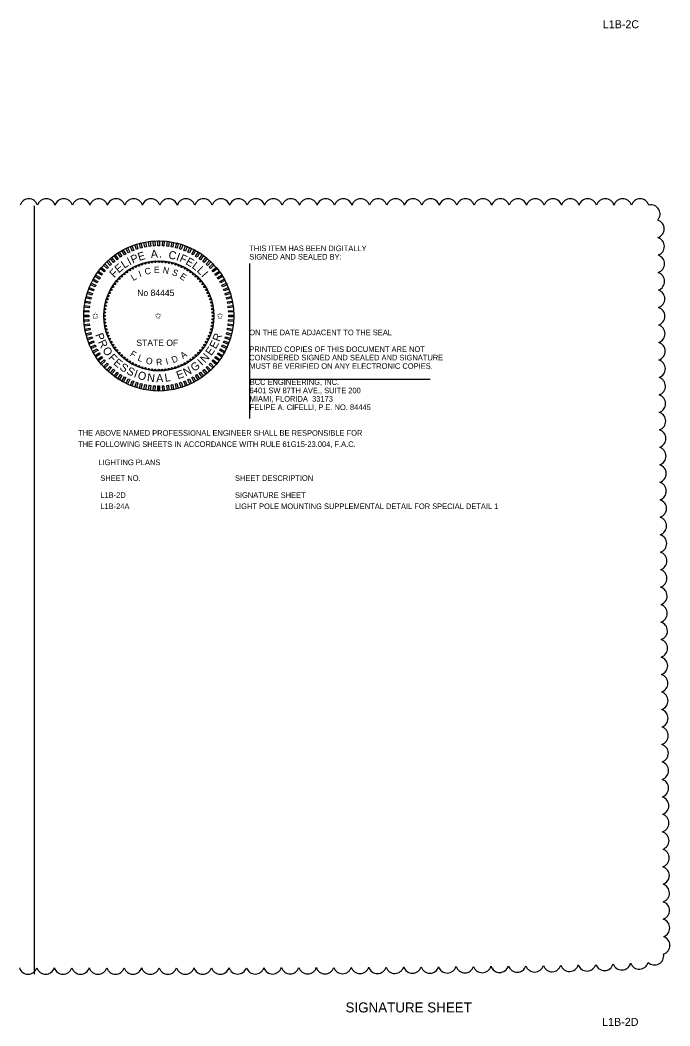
# Model space of a CAD drawing. Extents: x -811.2 to -755.6, y -2295.2 to -2235.1.
# Drawn here: x -803.27 to -795.14, y -2295.15 to -2282.59 of the extents above; entities that cross this region are included whole.
import ezdxf

# ---------------------------------------------------------------- set-up
doc = ezdxf.new("R2010")
doc.units = 0
for name, color, linetype in [('Cloud_dp', 7, 'Continuous'), ('Logo_dp', 7, 'Continuous'), ('NonPlottingEle_dp', 7, 'Continuous'), ('ScratchEle_dp', 7, 'Continuous'), ('SheetBorder_dp', 7, 'Continuous'), ('TextMisc', 7, 'Continuous'), ('TextNotes', 7, 'Continuous'), ('TextShtNo', 7, 'Continuous')]:
    doc.layers.add(name, color=color, linetype=linetype)

msp = doc.modelspace()

# ---------------------------------------------------------------- linework, layer by layer
at = {"layer": 'Cloud_dp'}
for centre, start, end in [((-803.157, -2284.933), 17.5, 162.5), ((-802.939, -2284.933), 17.5, 162.5), ((-802.721, -2284.933), 17.5, 162.5), ((-802.502, -2284.933), 17.5, 162.5), ((-802.284, -2284.933), 17.5, 162.5), ((-802.066, -2284.933), 17.5, 162.5), ((-801.847, -2284.933), 17.5, 162.5), ((-801.629, -2284.933), 17.5, 162.5), ((-801.411, -2284.933), 17.5, 162.5), ((-801.192, -2284.933), 17.5, 162.5), ((-800.974, -2284.933), 17.5, 162.5), ((-800.756, -2284.933), 17.5, 162.5), ((-800.537, -2284.933), 17.5, 162.5), ((-800.319, -2284.933), 17.5, 162.5), ((-800.101, -2284.933), 17.5, 162.5), ((-799.882, -2284.933), 17.5, 162.5), ((-799.664, -2284.933), 17.5, 162.5), ((-799.446, -2284.933), 17.5, 162.5), ((-799.227, -2284.933), 17.5, 162.5), ((-799.009, -2284.933), 17.5, 162.5), ((-798.791, -2284.933), 17.5, 162.5), ((-798.572, -2284.933), 17.5, 162.5), ((-798.354, -2284.933), 17.5, 162.5), ((-798.136, -2284.933), 17.5, 162.5), ((-797.917, -2284.933), 17.5, 162.5), ((-797.699, -2284.933), 17.5, 162.5), ((-797.481, -2284.933), 17.5, 162.5), ((-797.262, -2284.933), 17.5, 162.5), ((-797.044, -2284.933), 17.5, 162.5), ((-796.826, -2284.933), 17.5, 162.5), ((-796.607, -2284.933), 17.5, 162.5), ((-796.389, -2284.933), 17.5, 162.5), ((-796.171, -2284.933), 17.5, 162.5), ((-795.952, -2284.933), 17.5, 162.5), ((-795.734, -2284.933), 17.5, 162.5), ((-795.516, -2284.933), 17.5, 162.5), ((-795.381, -2285.01), 318.1116, 103.1116), ((-795.329, -2285.196), 287.9529, 72.9529), ((-795.327, -2285.414), 287.9529, 72.9529), ((-795.326, -2285.632), 287.9529, 72.9529), ((-795.324, -2285.851), 287.9529, 72.9529), ((-795.322, -2286.069), 287.9529, 72.9529), ((-795.32, -2286.287), 287.9529, 72.9529), ((-795.319, -2286.506), 287.9529, 72.9529), ((-795.317, -2286.724), 287.9529, 72.9529), ((-795.315, -2286.942), 287.9529, 72.9529), ((-795.314, -2287.16), 287.9529, 72.9529), ((-795.312, -2287.379), 287.9529, 72.9529), ((-795.31, -2287.597), 287.9529, 72.9529), ((-795.308, -2287.815), 287.9529, 72.9529), ((-795.307, -2288.034), 287.9529, 72.9529), ((-795.305, -2288.252), 287.9529, 72.9529), ((-795.303, -2288.47), 287.9529, 72.9529), ((-795.301, -2288.689), 287.9529, 72.9529), ((-795.3, -2288.907), 287.9529, 72.9529), ((-795.298, -2289.125), 287.9529, 72.9529), ((-795.296, -2289.344), 287.9529, 72.9529), ((-795.295, -2289.562), 287.9529, 72.9529), ((-795.293, -2289.78), 287.9527, 72.9527), ((-795.291, -2289.999), 287.9524, 72.9524), ((-795.289, -2290.217), 287.9521, 72.9521), ((-795.288, -2290.435), 287.9519, 72.9519), ((-795.286, -2290.654), 287.9515, 72.9515), ((-795.284, -2290.872), 287.9512, 72.9512), ((-795.282, -2291.09), 287.9508, 72.9508), ((-795.281, -2291.309), 287.9504, 72.9504), ((-795.279, -2291.527), 287.9499, 72.9499), ((-795.277, -2291.745), 287.9494, 72.9494), ((-795.276, -2291.963), 287.9488, 72.9488), ((-795.274, -2292.182), 287.9481, 72.9481), ((-795.272, -2292.4), 287.9473, 72.9473), ((-795.271, -2292.618), 287.9464, 72.9464), ((-795.269, -2292.837), 287.9452, 72.9452), ((-795.267, -2293.055), 287.9438, 72.9438), ((-795.265, -2293.273), 287.9419, 72.9419), ((-795.264, -2293.492), 287.9394, 72.9394), ((-795.262, -2293.71), 287.9355, 72.9355), ((-795.26, -2293.928), 287.9288, 72.9288), ((-795.259, -2294.147), 287.9106, 72.9106), ((-795.336, -2294.276), 225.4798, 10.4798), ((-803.166, -2294.393), 197.496, 342.496), ((-802.948, -2294.393), 197.5011, 342.5011), ((-802.729, -2294.393), 197.5111, 342.5111), ((-802.511, -2294.393), 197.522, 342.522), ((-802.293, -2294.393), 197.5335, 342.5335), ((-802.074, -2294.393), 197.5456, 342.5456), ((-801.856, -2294.393), 197.5582, 342.5582), ((-801.638, -2294.392), 197.5715, 342.5715), ((-801.42, -2294.392), 197.5855, 342.5855), ((-801.201, -2294.392), 197.6002, 342.6002), ((-800.983, -2294.391), 197.6157, 342.6157), ((-800.765, -2294.391), 197.6322, 342.6322), ((-800.546, -2294.39), 197.6497, 342.6497), ((-800.328, -2294.39), 197.6683, 342.6683), ((-800.11, -2294.389), 197.6881, 342.6881), ((-799.891, -2294.388), 197.7093, 342.7093), ((-799.673, -2294.387), 197.732, 342.732), ((-799.455, -2294.387), 197.7565, 342.7565), ((-799.236, -2294.386), 197.7829, 342.7829), ((-799.018, -2294.384), 197.8116, 342.8116), ((-798.8, -2294.383), 197.8429, 342.8429), ((-798.582, -2294.382), 197.8771, 342.8771), ((-798.363, -2294.38), 197.9149, 342.9149), ((-798.145, -2294.379), 197.9569, 342.9569), ((-797.927, -2294.377), 198.0039, 343.0039), ((-797.708, -2294.375), 198.0569, 343.0569), ((-797.49, -2294.373), 198.1174, 343.1174), ((-797.272, -2294.37), 198.1874, 343.1874), ((-797.054, -2294.367), 198.2696, 343.2696), ((-796.835, -2294.364), 198.368, 343.368), ((-796.617, -2294.361), 198.4888, 343.4888), ((-796.399, -2294.357), 198.642, 343.642), ((-796.181, -2294.352), 198.8454, 343.8454), ((-795.963, -2294.346), 199.1345, 344.1345), ((-795.745, -2294.339), 199.5943, 344.5943), ((-795.527, -2294.329), 200.5167, 345.5167)]:
    msp.add_arc(centre, 0.114, start, end, dxfattribs=at)
at = {"layer": 'Logo_dp'}
for p, q in [((-801.543, -2287.22), (-801.543, -2287.158)), ((-801.533, -2287.22), (-801.533, -2287.158)), ((-801.523, -2287.22), (-801.523, -2287.158))]:
    msp.add_line(p, q, dxfattribs=at)
for points in [[(-801.794, -2285.447), (-801.813, -2285.454), (-801.832, -2285.394), (-801.813, -2285.388)], [(-801.741, -2285.433), (-801.76, -2285.438), (-801.776, -2285.377), (-801.756, -2285.372)], [(-801.687, -2285.421), (-801.707, -2285.425), (-801.718, -2285.364), (-801.699, -2285.36)], [(-801.632, -2285.413), (-801.653, -2285.416), (-801.66, -2285.354), (-801.64, -2285.351)], [(-801.578, -2285.409), (-801.598, -2285.41), (-801.602, -2285.348), (-801.582, -2285.346)], [(-801.523, -2285.408), (-801.543, -2285.408), (-801.543, -2285.345), (-801.523, -2285.345)], [(-801.468, -2285.41), (-801.488, -2285.409), (-801.484, -2285.346), (-801.464, -2285.348)], [(-801.413, -2285.416), (-801.433, -2285.413), (-801.425, -2285.351), (-801.405, -2285.354)], [(-801.359, -2285.425), (-801.379, -2285.421), (-801.367, -2285.36), (-801.347, -2285.364)], [(-801.305, -2285.438), (-801.325, -2285.433), (-801.309, -2285.372), (-801.29, -2285.377)], [(-801.253, -2285.454), (-801.272, -2285.447), (-801.253, -2285.388), (-801.234, -2285.394)], [(-802.039, -2285.569), (-802.055, -2285.581), (-802.092, -2285.53), (-802.076, -2285.518)], [(-801.993, -2285.538), (-802.01, -2285.549), (-802.044, -2285.497), (-802.027, -2285.486)], [(-801.946, -2285.511), (-801.963, -2285.521), (-801.993, -2285.466), (-801.976, -2285.456)], [(-801.896, -2285.487), (-801.915, -2285.495), (-801.941, -2285.439), (-801.923, -2285.43)], [(-801.846, -2285.465), (-801.864, -2285.473), (-801.887, -2285.415), (-801.869, -2285.407)], [(-801.201, -2285.473), (-801.22, -2285.465), (-801.197, -2285.407), (-801.178, -2285.415)], [(-801.151, -2285.495), (-801.169, -2285.487), (-801.143, -2285.43), (-801.125, -2285.439)], [(-801.102, -2285.521), (-801.12, -2285.511), (-801.09, -2285.456), (-801.072, -2285.466)], [(-801.055, -2285.549), (-801.073, -2285.539), (-801.039, -2285.486), (-801.022, -2285.497)], [(-801.01, -2285.581), (-801.027, -2285.569), (-800.99, -2285.518), (-800.974, -2285.53)], [(-802.164, -2285.676), (-802.178, -2285.691), (-802.223, -2285.648), (-802.209, -2285.634)], [(-802.124, -2285.638), (-802.139, -2285.652), (-802.182, -2285.606), (-802.167, -2285.592)], [(-802.083, -2285.602), (-802.098, -2285.615), (-802.138, -2285.567), (-802.123, -2285.554)], [(-800.967, -2285.615), (-800.983, -2285.602), (-800.943, -2285.554), (-800.928, -2285.567)], [(-800.926, -2285.652), (-800.941, -2285.638), (-800.898, -2285.592), (-800.884, -2285.606)], [(-800.888, -2285.691), (-800.902, -2285.676), (-800.856, -2285.634), (-800.843, -2285.648)], [(-802.266, -2285.805), (-802.277, -2285.822), (-802.33, -2285.789), (-802.319, -2285.772)], [(-802.235, -2285.76), (-802.247, -2285.776), (-802.297, -2285.74), (-802.285, -2285.723)], [(-802.201, -2285.717), (-802.214, -2285.733), (-802.262, -2285.693), (-802.249, -2285.677)], [(-800.852, -2285.733), (-800.865, -2285.717), (-800.817, -2285.677), (-800.804, -2285.693)], [(-800.819, -2285.777), (-800.831, -2285.76), (-800.78, -2285.724), (-800.769, -2285.74)], [(-800.789, -2285.822), (-800.799, -2285.805), (-800.747, -2285.772), (-800.736, -2285.789)], [(-802.32, -2285.901), (-802.329, -2285.919), (-802.385, -2285.893), (-802.377, -2285.874)], [(-802.295, -2285.852), (-802.305, -2285.87), (-802.359, -2285.84), (-802.35, -2285.822)], [(-800.761, -2285.87), (-800.771, -2285.852), (-800.716, -2285.822), (-800.707, -2285.84)], [(-800.737, -2285.919), (-800.745, -2285.901), (-800.689, -2285.875), (-800.68, -2285.893)], [(-802.362, -2286.003), (-802.368, -2286.022), (-802.428, -2286.003), (-802.421, -2285.983)], [(-802.343, -2285.951), (-802.35, -2285.97), (-802.408, -2285.947), (-802.401, -2285.928)], [(-800.716, -2285.97), (-800.723, -2285.951), (-800.665, -2285.928), (-800.658, -2285.947)], [(-800.698, -2286.022), (-800.704, -2286.003), (-800.644, -2285.984), (-800.638, -2286.003)], [(-802.4, -2286.163), (-802.402, -2286.183), (-802.464, -2286.175), (-802.462, -2286.155)], [(-802.391, -2286.109), (-802.394, -2286.129), (-802.456, -2286.117), (-802.452, -2286.097)], [(-802.378, -2286.055), (-802.383, -2286.075), (-802.443, -2286.059), (-802.438, -2286.04)], [(-800.683, -2286.075), (-800.688, -2286.055), (-800.627, -2286.04), (-800.622, -2286.059)], [(-800.671, -2286.129), (-800.675, -2286.109), (-800.614, -2286.097), (-800.61, -2286.117)], [(-800.664, -2286.183), (-800.666, -2286.163), (-800.604, -2286.155), (-800.602, -2286.175)], [(-802.408, -2286.273), (-802.408, -2286.293), (-802.47, -2286.293), (-802.47, -2286.273)], [(-802.406, -2286.218), (-802.407, -2286.238), (-802.469, -2286.234), (-802.468, -2286.214)], [(-800.659, -2286.238), (-800.66, -2286.218), (-800.598, -2286.214), (-800.597, -2286.234)], [(-800.658, -2286.293), (-800.658, -2286.273), (-800.595, -2286.273), (-800.595, -2286.293)], [(-802.407, -2286.327), (-802.406, -2286.348), (-802.468, -2286.352), (-802.469, -2286.331)], [(-802.402, -2286.382), (-802.4, -2286.402), (-802.462, -2286.41), (-802.464, -2286.39)], [(-800.666, -2286.402), (-800.664, -2286.382), (-800.602, -2286.39), (-800.604, -2286.41)], [(-800.66, -2286.348), (-800.659, -2286.328), (-800.597, -2286.332), (-800.598, -2286.352)], [(-802.394, -2286.437), (-802.391, -2286.456), (-802.452, -2286.468), (-802.456, -2286.448)], [(-802.383, -2286.49), (-802.378, -2286.51), (-802.438, -2286.526), (-802.443, -2286.506)], [(-800.688, -2286.51), (-800.683, -2286.491), (-800.622, -2286.506), (-800.627, -2286.526)], [(-800.675, -2286.457), (-800.672, -2286.437), (-800.61, -2286.449), (-800.614, -2286.468)], [(-802.368, -2286.543), (-802.362, -2286.563), (-802.421, -2286.582), (-802.428, -2286.563)], [(-802.35, -2286.595), (-802.343, -2286.614), (-802.401, -2286.637), (-802.408, -2286.618)], [(-802.329, -2286.646), (-802.32, -2286.664), (-802.377, -2286.691), (-802.386, -2286.673)], [(-800.746, -2286.664), (-800.737, -2286.646), (-800.68, -2286.673), (-800.689, -2286.691)], [(-800.723, -2286.614), (-800.716, -2286.596), (-800.658, -2286.619), (-800.665, -2286.637)], [(-800.704, -2286.563), (-800.698, -2286.544), (-800.638, -2286.563), (-800.644, -2286.582)], [(-802.305, -2286.695), (-802.295, -2286.713), (-802.35, -2286.743), (-802.359, -2286.725)], [(-802.277, -2286.743), (-802.266, -2286.76), (-802.319, -2286.793), (-802.33, -2286.776)], [(-800.8, -2286.76), (-800.789, -2286.743), (-800.736, -2286.777), (-800.747, -2286.794)], [(-800.771, -2286.713), (-800.761, -2286.695), (-800.707, -2286.726), (-800.716, -2286.743)], [(-802.247, -2286.789), (-802.235, -2286.805), (-802.285, -2286.842), (-802.297, -2286.826)], [(-802.214, -2286.833), (-802.201, -2286.848), (-802.249, -2286.888), (-802.262, -2286.872)], [(-802.178, -2286.874), (-802.164, -2286.889), (-802.209, -2286.932), (-802.223, -2286.917)], [(-800.902, -2286.889), (-800.888, -2286.874), (-800.843, -2286.917), (-800.857, -2286.932)], [(-800.865, -2286.848), (-800.852, -2286.833), (-800.804, -2286.873), (-800.817, -2286.888)], [(-800.831, -2286.805), (-800.819, -2286.789), (-800.769, -2286.826), (-800.78, -2286.842)], [(-802.139, -2286.914), (-802.125, -2286.927), (-802.167, -2286.973), (-802.182, -2286.959)], [(-802.099, -2286.95), (-802.083, -2286.963), (-802.123, -2287.011), (-802.138, -2286.999)], [(-802.055, -2286.985), (-802.039, -2286.997), (-802.076, -2287.047), (-802.092, -2287.035)], [(-802.01, -2287.016), (-801.993, -2287.027), (-802.027, -2287.08), (-802.044, -2287.069)], [(-801.073, -2287.027), (-801.056, -2287.016), (-801.022, -2287.069), (-801.039, -2287.08)], [(-801.027, -2286.997), (-801.011, -2286.985), (-800.974, -2287.035), (-800.99, -2287.047)], [(-800.983, -2286.963), (-800.967, -2286.951), (-800.928, -2286.999), (-800.943, -2287.012)], [(-800.941, -2286.928), (-800.927, -2286.914), (-800.884, -2286.959), (-800.899, -2286.973)], [(-801.963, -2287.045), (-801.946, -2287.054), (-801.976, -2287.109), (-801.993, -2287.099)], [(-801.915, -2287.07), (-801.896, -2287.079), (-801.923, -2287.135), (-801.941, -2287.127)], [(-801.865, -2287.093), (-801.846, -2287.1), (-801.869, -2287.158), (-801.887, -2287.151)], [(-801.813, -2287.112), (-801.794, -2287.118), (-801.813, -2287.177), (-801.832, -2287.171)], [(-801.76, -2287.128), (-801.741, -2287.133), (-801.756, -2287.193), (-801.776, -2287.188)], [(-801.707, -2287.14), (-801.687, -2287.144), (-801.699, -2287.205), (-801.719, -2287.202)], [(-801.653, -2287.15), (-801.633, -2287.152), (-801.64, -2287.214), (-801.661, -2287.212)], [(-801.598, -2287.155), (-801.578, -2287.157), (-801.582, -2287.219), (-801.602, -2287.218)], [(-801.543, -2287.158), (-801.523, -2287.158), (-801.523, -2287.22), (-801.543, -2287.22)], [(-801.488, -2287.157), (-801.468, -2287.155), (-801.464, -2287.218), (-801.484, -2287.219)], [(-801.433, -2287.152), (-801.413, -2287.15), (-801.406, -2287.212), (-801.426, -2287.214)], [(-801.379, -2287.144), (-801.359, -2287.14), (-801.347, -2287.202), (-801.367, -2287.205)], [(-801.325, -2287.133), (-801.306, -2287.128), (-801.29, -2287.188), (-801.31, -2287.193)], [(-801.272, -2287.118), (-801.253, -2287.112), (-801.234, -2287.171), (-801.253, -2287.177)], [(-801.22, -2287.1), (-801.202, -2287.093), (-801.179, -2287.151), (-801.197, -2287.158)], [(-801.17, -2287.079), (-801.151, -2287.07), (-801.125, -2287.127), (-801.143, -2287.135)], [(-801.12, -2287.054), (-801.103, -2287.045), (-801.073, -2287.099), (-801.09, -2287.109)]]:
    msp.add_lwpolyline(points, close=True, dxfattribs=at)
for centre in [(-801.782, -2285.653), (-801.742, -2285.638), (-801.701, -2285.626), (-801.659, -2285.617), (-801.617, -2285.611), (-801.575, -2285.607), (-801.532, -2285.605), (-801.49, -2285.607), (-801.447, -2285.611), (-801.405, -2285.617), (-801.364, -2285.627), (-801.323, -2285.639), (-801.283, -2285.653), (-801.996, -2285.788), (-801.964, -2285.76), (-801.931, -2285.734), (-801.895, -2285.71), (-801.859, -2285.689), (-801.821, -2285.669), (-801.244, -2285.67), (-801.206, -2285.689), (-801.169, -2285.711), (-801.134, -2285.735), (-801.101, -2285.761), (-801.069, -2285.789), (-802.081, -2285.884), (-802.055, -2285.85), (-802.026, -2285.819), (-801.039, -2285.819), (-801.011, -2285.851), (-800.985, -2285.885), (-802.163, -2286.033), (-802.146, -2285.994), (-802.126, -2285.956), (-802.105, -2285.919), (-800.961, -2285.92), (-800.939, -2285.957), (-800.92, -2285.995), (-800.903, -2286.034), (-802.198, -2286.155), (-802.189, -2286.114), (-802.177, -2286.073), (-800.888, -2286.074), (-800.877, -2286.115), (-800.867, -2286.156), (-802.21, -2286.282), (-802.209, -2286.24), (-802.205, -2286.197), (-800.861, -2286.198), (-800.857, -2286.241), (-800.855, -2286.283), (-802.209, -2286.325), (-802.205, -2286.367), (-802.198, -2286.409), (-800.868, -2286.41), (-800.861, -2286.368), (-800.857, -2286.326), (-802.189, -2286.451), (-802.177, -2286.492), (-802.163, -2286.532), (-800.903, -2286.533), (-800.889, -2286.493), (-800.877, -2286.452), (-802.146, -2286.571), (-802.127, -2286.609), (-802.105, -2286.645), (-800.961, -2286.646), (-800.94, -2286.61), (-800.92, -2286.572), (-802.081, -2286.68), (-802.055, -2286.714), (-802.027, -2286.746), (-801.997, -2286.776), (-801.07, -2286.777), (-801.039, -2286.747), (-801.011, -2286.715), (-800.985, -2286.681), (-801.965, -2286.804), (-801.932, -2286.83), (-801.896, -2286.854), (-801.86, -2286.876), (-801.822, -2286.895), (-801.783, -2286.912), (-801.284, -2286.913), (-801.245, -2286.896), (-801.207, -2286.877), (-801.17, -2286.855), (-801.135, -2286.831), (-801.102, -2286.805), (-801.743, -2286.927), (-801.702, -2286.939), (-801.66, -2286.948), (-801.618, -2286.955), (-801.576, -2286.959), (-801.533, -2286.96), (-801.491, -2286.959), (-801.449, -2286.955), (-801.407, -2286.948), (-801.365, -2286.939), (-801.324, -2286.927)]:
    msp.add_circle(centre, 0.01, dxfattribs=at)
at = {"layer": 'NonPlottingEle_dp'}
for radius in [0.938, 0.688]:
    msp.add_circle((-801.533, -2286.283), radius, dxfattribs=at)
at = {"layer": 'ScratchEle_dp'}
for p, q in [((-800.397, -2285.629), (-800.397, -2287.564)), ((-800.397, -2287.074), (-798.141, -2287.074))]:
    msp.add_line(p, q, dxfattribs=at)
at = {"layer": 'SheetBorder_dp'}
msp.add_line((-803.086, -2294.507), (-803.086, -2284.907), dxfattribs=at)

# ---------------------------------------------------------------- texts
at = {"layer": 'Logo_dp'}
for s, height, rotation, p in [('P', 0.1, 23.2829, (-801.858, -2285.631)), ('E', 0.1, 16.5426, (-801.779, -2285.597)), ('A', 0.1, 4.421, (-801.63, -2285.561)), ('C', 0.1, 347.7999, (-801.419, -2285.563)), ('I', 0.1, 340.0631, (-801.323, -2285.585)), ('F', 0.1, 336.5299, (-801.281, -2285.599)), ('E', 0.1, 40.1214, (-802.033, -2285.753)), ('L', 0.1, 33.0792, (-801.964, -2285.695)), ('I', 0.1, 26.8161, (-801.898, -2285.652)), ('.', 0.1, 356.654, (-801.531, -2285.554)), ('E', 0.1, 330.0796, (-801.206, -2285.632)), ('L', 0.1, 323.0373, (-801.128, -2285.677)), ('F', 0.1, 46.5718, (-802.089, -2285.812)), ('L', 0.08, 30.4021, (-801.852, -2285.849)), ('I', 0.08, 20.0117, (-801.769, -2285.799)), ('C', 0.08, 12.2025, (-801.701, -2285.771)), ('E', 0.08, 0.4186, (-801.593, -2285.748)), ('N', 0.08, 349.2914, (-801.488, -2285.746)), ('S', 0.08, 337.0221, (-801.375, -2285.768)), ('E', 0.08, 325.8663, (-801.279, -2285.808)), ('L', 0.1, 316.7742, (-801.065, -2285.725)), ('I', 0.1, 310.5111, (-801.006, -2285.779)), ('P', 0.1, 289.4055, (-802.328, -2286.517)), ('R', 0.1, 69.5134, (-800.773, -2286.612)), ('R', 0.1, 296.1458, (-802.295, -2286.609)), ('E', 0.1, 62.4712, (-800.819, -2286.703)), ('O', 0.1, 303.9671, (-802.243, -2286.71)), ('F', 0.1, 312.628, (-802.171, -2286.812)), ('F', 0.08, 328.7241, (-801.901, -2286.779)), ('L', 0.08, 339.2916, (-801.804, -2286.838)), ('D', 0.08, 22.0128, (-801.355, -2286.875)), ('A', 0.08, 34.4992, (-801.231, -2286.822)), ('N', 0.1, 47.1788, (-800.955, -2286.877)), ('E', 0.1, 55.4289, (-800.876, -2286.787)), ('E', 0.1, 319.0783, (-802.107, -2286.88)), ('S', 0.1, 326.1206, (-802.03, -2286.946)), ('O', 0.08, 349.6821, (-801.699, -2286.878)), ('R', 0.08, 2.3398, (-801.565, -2286.9)), ('I', 0.08, 14.2037, (-801.437, -2286.893)), ('N', 0.1, 26.8614, (-801.197, -2287.04)), ('G', 0.1, 35.1115, (-801.092, -2286.984)), ('I', 0.1, 43.6456, (-800.993, -2286.911)), ('S', 0.1, 333.193, (-801.944, -2287.002)), ('I', 0.1, 340.2654, (-801.853, -2287.047)), ('O', 0.1, 343.7986, (-801.805, -2287.065)), ('N', 0.1, 352.4595, (-801.684, -2287.097)), ('A', 0.1, 0.7097, (-801.565, -2287.111)), ('L', 0.1, 8.4767, (-801.453, -2287.107)), ('E', 0.1, 19.8191, (-801.293, -2287.076))]:
    msp.add_text(s, height=height, rotation=rotation, dxfattribs=at).set_placement(p)
for s, p in [('No 84445', (-801.802, -2286.035)), ('✩', (-802.368, -2286.321)), ('✩', (-801.583, -2286.321)), ('✩', (-800.811, -2286.321)), ('STATE OF', (-801.813, -2286.659))]:
    msp.add_text(s, height=0.08, dxfattribs=at).set_placement(p)
at = {"layer": 'TextMisc'}
for s, height, p in [('THIS ITEM HAS BEEN DIGITALLY', 0.07, (-800.402, -2285.474)), ('SIGNED AND SEALED BY:', 0.07, (-800.402, -2285.579)), ('ON THE DATE ADJACENT TO THE SEAL', 0.07, (-800.402, -2286.524)), ('CONSIDERED SIGNED AND SEALED AND SIGNATURE ', 0.07, (-800.402, -2286.839)), ('PRINTED COPIES OF THIS DOCUMENT ARE NOT ', 0.07, (-800.402, -2286.734)), ('MUST BE VERIFIED ON ANY ELECTRONIC COPIES.', 0.07, (-800.402, -2286.944)), ('BCC ENGINEERING, INC.', 0.07, (-800.397, -2287.144)), ('6401 SW 87TH AVE., SUITE 200', 0.07, (-800.397, -2287.249)), ('MIAMI, FLORIDA  33173', 0.07, (-800.397, -2287.354)), ('FELIPE A. CIFELLI, P.E. NO. 84445', 0.07, (-800.397, -2287.459)), ('THE ABOVE NAMED PROFESSIONAL ENGINEER SHALL BE RESPONSIBLE FOR ', 0.07, (-802.541, -2287.78)), ('THE FOLLOWING SHEETS IN ACCORDANCE WITH RULE 61G15-23.004, F.A.C.', 0.07, (-802.541, -2287.92)), ('LIGHTING PLANS', 0.07, (-802.288, -2288.147)), ('       SIGNATURE SHEET         ', 0.125, (-799.524, -2294.983))]:
    msp.add_text(s, height=height, dxfattribs=at).set_placement(p)
at = {"layer": 'TextNotes'}
for s, p in [('SHEET NO.', (-802.264, -2288.344)), ('SHEET DESCRIPTION', (-800.581, -2288.344)), ('L1B-2D', (-802.264, -2288.556)), ('SIGNATURE SHEET', (-800.581, -2288.556)), ('L1B-24A', (-802.264, -2288.696)), ('LIGHT POLE MOUNTING SUPPLEMENTAL DETAIL FOR SPECIAL DETAIL 1', (-800.581, -2288.696))]:
    msp.add_text(s, height=0.07, dxfattribs=at).set_placement(p)
at = {"layer": 'TextShtNo'}
for s, p in [('L1B-2C ', (-795.983, -2282.69)), ('L1B-2D ', (-795.991, -2295.151))]:
    msp.add_text(s, height=0.1, dxfattribs=at).set_placement(p)

doc.saveas('drawing.dxf')
